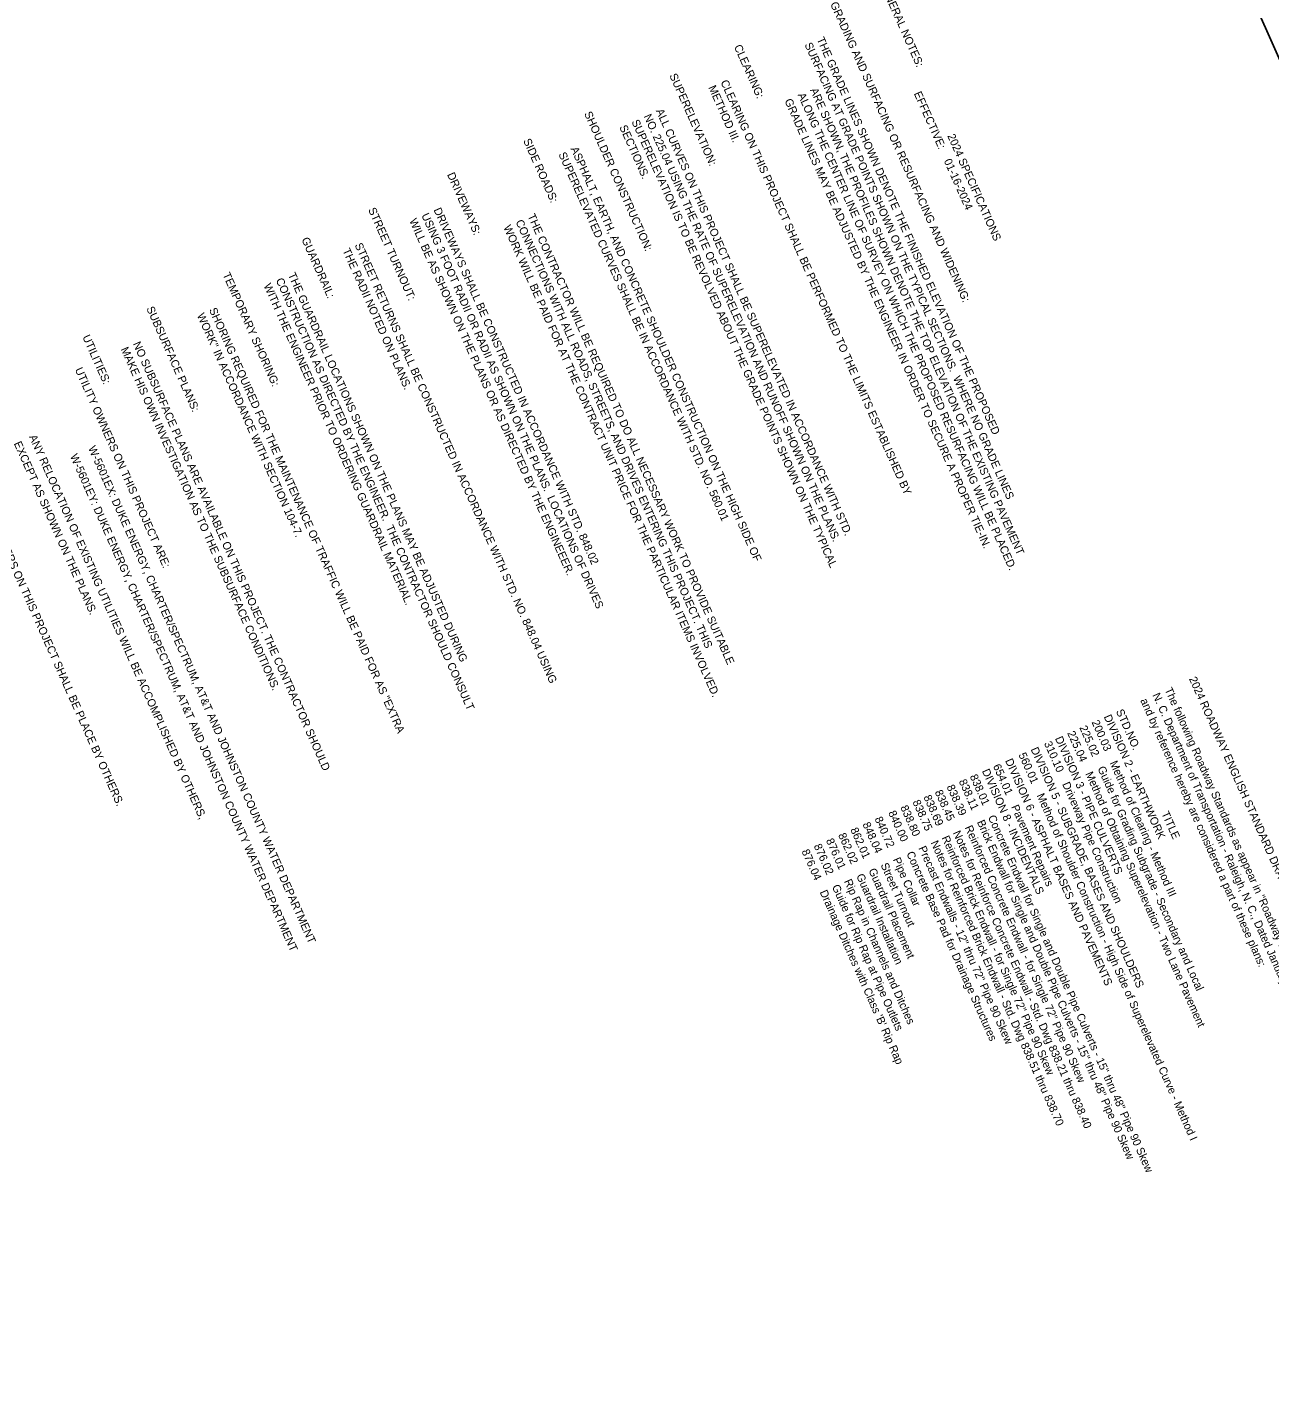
# Model space of a CAD drawing. Extents: x 885268 to 886953, y 552794 to 554777.
# Drawn here: x 885831 to 886576, y 553214 to 554037 of the extents above; entities that cross this region are included whole.
import ezdxf

# ---------------------------------------------------------------- set-up
doc = ezdxf.new("R2010")
doc.units = 0
doc.layers.add('Default', color=7, linetype='Continuous')
doc.layers.add('Sheet Plan CELL', color=7, linetype='Continuous')

msp = doc.modelspace()

# ---------------------------------------------------------------- linework, layer by layer
at = {"layer": 'Sheet Plan CELL'}
msp.add_lwpolyline([(886925.82, 553245.96), (886315.6, 554616.23), (885356.41, 554189.08), (885966.63, 552818.81)], close=True, dxfattribs=at)

# ---------------------------------------------------------------- texts
at = {"layer": 'Default'}
for s, p in [('GENERAL NOTES:                         2024 SPECIFICATIONS', (886341.44, 554064.16)), ('GRADING AND SURFACING OR RESURFACING AND WIDENING:  ', (886312.21, 554051.14)), ('         THE GRADE LINES SHOWN DENOTE THE FINISHED ELEVATION OF THE PROPOSED ', (886297.6, 554044.63)), ('CLEARING:  ', (886254.51, 554025.45)), ('         SURFACING AT GRADE POINTS SHOWN ON THE TYPICAL SECTIONS.  WHERE NO GRADE LINES', (886290.29, 554041.38)), ('SUPERELEVATION:  ', (886215.74, 554008.18)), ('         METHOD III.', (886232.59, 554015.68)), ('         CLEARING ON THIS PROJECT SHALL BE PERFORMED TO THE LIMITS ESTABLISHED BY ', (886239.9, 554018.94)), ('ARE SHOWN, THE PROFILES SHOWN DENOTE THE TOP ELEVATION OF THE EXISTING PAVEMENT', (886300.17, 553999.51)), ('                                       EFFECTIVE:    01-16-2024', (886334.14, 554060.9)), ('GRADE LINES MAY BE ADJUSTED BY THE ENGINEER IN ORDER TO SECURE A PROPER TIE-IN.', (886284.8, 553993.04)), ('ALONG THE CENTER LINE OF SURVEY ON WHICH THE PROPOSED RESURFACING WILL BE PLACED.', (886292.73, 553996.57)), ('SHOULDER CONSTRUCTION:  ', (886164.58, 553985.4)), ('         SUPERELEVATION IS TO BE REVOLVED ABOUT THE GRADE POINTS SHOWN ON THE TYPICAL ', (886186.5, 553995.16)), ('         NO. 225.04 USING THE RATE OF SUPERELEVATION AND RUNOFF SHOWN ON THE PLANS.', (886193.81, 553998.41)), ('         ALL CURVES ON THIS PROJECT SHALL BE SUPERELEVATED IN ACCORDANCE WITH STD. ', (886201.12, 554001.67)), ('         SECTIONS.  ', (886179.2, 553991.9)), ('SIDE ROADS:  ', (886128.04, 553969.12)), ('         SUPERELEVATED CURVES SHALL BE IN ACCORDANCE WITH STD. NO. 560.01', (886142.65, 553975.63)), ('         ASPHALT, EARTH, AND CONCRETE SHOULDER CONSTRUCTION ON THE HIGH SIDE OF', (886149.96, 553978.89)), ('DRIVEWAYS:  ', (886082.35, 553948.78)), ('STREET TURNOUT:  ', (886035.01, 553927.69)), ('         USING 3 FOOT RADII OR RADII AS SHOWN ON THE PLANS.  LOCATIONS OF DRIVES', (886060.42, 553939.01)), ('         DRIVEWAYS SHALL BE CONSTRUCTED IN ACCORDANCE WITH STD. 848.02', (886067.73, 553942.27)), ('THE CONTRACTOR WILL BE REQUIRED TO DO ALL NECESSARY WORK TO PROVIDE SUITABLE', (886130.62, 553924)), ('         WILL BE AS SHOWN ON THE PLANS OR AS DIRECTED BY THE ENGINEEER.', (886053.12, 553935.76)), ('WORK WILL BE PAID FOR AT THE CONTRACT UNIT PRICE FOR THE PARTICULAR ITEMS INVOLVED.', (886116.14, 553917.18)), ('CONNECTIONS WITH ALL ROADS, STREETS, AND DRIVES ENTERING THIS PROJECT. THIS', (886123.45, 553920.44)), ('GUARDRAIL:  ', (885994.98, 553909.87)), ('         STREET RETURNS SHALL BE CONSTRUCTED IN ACCORDANCE WITH STD. NO. 848.04 USING', (886020.39, 553921.19)), ('         THE RADII NOTED ON PLANS.', (886013.08, 553917.93)), ('TEMPORARY SHORING:  ', (885947.64, 553888.79)), ('         WITH THE ENGINEER PRIOR TO ORDERING GUARDRAIL MATERIAL.', (885965.75, 553896.85)), ('         CONSTRUCTION AS DIRECTED BY THE ENGINEER.  THE CONTRACTOR SHOULD CONSULT', (885973.05, 553900.11)), ('         THE GUARDRAIL LOCATIONS SHOWN ON THE PLANS MAY BE ADJUSTED DURING ', (885980.36, 553903.36)), ('SUBSURFACE PLANS:  ', (885901.95, 553868.44)), ('         WORK" IN ACCORDANCE WITH SECTION 104-7.', (885925.72, 553879.02)), ('         SHORING REQUIRED FOR THE MAINTENANCE OF TRAFFIC WILL BE PAID FOR AS "EXTRA ', (885933.02, 553882.28)), ('UTILITIES:  ', (885863.57, 553851.35)), ('         MAKE HIS OWN INVESTIGATION AS TO THE SUBSURFACE CONDITIONS. ', (885880.03, 553858.68)), ('         NO SUBSURFACE PLANS ARE AVAILABLE ON THIS PROJECT. THE CONTRACTOR SHOULD', (885887.33, 553861.93)), ('         UTILITY OWNERS ON THIS PROJECT ARE:  ', (885852.51, 553846.43)), ('         ALL RIGHT-OF-WAY MARKERS ON THIS PROJECT SHALL BE PLACE BY OTHERS.', (885776.24, 553812.46)), ('EXCEPT AS SHOWN ON THE PLANS.', (885822.4, 553787.45)), ('ANY RELOCATION OF EXISTING UTILITIES WILL BE ACCOMPLISHED BY OTHERS,', (885831.51, 553791.5)), ('W-5601EX: DUKE ENERGY, CHARTER/SPECTRUM, AT&T AND JOHNSTON COUNTY WATER DEPARTMENT', (885866.97, 553784.7)), ('W-5601EY: DUKE ENERGY, CHARTER/SPECTRUM, AT&T AND JOHNSTON COUNTY WATER DEPARTMENT', (885856.1, 553779.86)), ('2024 ROADWAY ENGLISH STANDARD DRAWINGS', (886527.52, 553646.3)), ('N. C. Department of Transportation - Raleigh, N. C., Dated January, 2024 are applicable to this project', (886505.6, 553636.54)), ('The following Roadway Standards as appear in "Roadway Standard Drawings" Highway Design Branch -', (886512.91, 553639.79)), ('STD.NO.                       TITLE', (886483.68, 553626.77)), ('and by reference hereby are considered a part of these plans:', (886498.29, 553633.28)), ('200.03    Method of Clearing - Method III', (886469.06, 553620.26)), ('DIVISION 2 - EARTHWORK', (886476.37, 553623.52)), ('DIVISION 3 - PIPE CULVERTS', (886447.14, 553610.5)), ('225.04    Method of Obtaining Superelevation - Two Lane Pavement', (886454.44, 553613.75)), ('225.02    Guide for Grading Subgrade - Secondary and Local', (886461.75, 553617.01)), ('DIVISION 5 - SUBGRADE, BASES AND SHOULDERS', (886432.52, 553603.99)), ('310.10    Driveway Pipe Construction ', (886440.54, 553607.56)), ('654.01    Pavement Repairs', (886409.88, 553593.91)), ('DIVISION 6 - ASPHALT BASES AND PAVEMENTS', (886417.19, 553597.17)), ('560.01    Method of Shoulder Construction - High Side of Superelevated Curve - Method I', (886425.21, 553600.74)), ('838.11    Brick Endwall for Single and Double Pipe Culverts - 15" thru 48" Pipe 90 Skew', (886389.4, 553584.79)), ('838.01    Concrete Endwall for Single and Double Pipe Culverts - 15" thru 48" Pipe 90 Skew', (886395.98, 553587.72)), ('DIVISION 8 - INCIDENTALS', (886403.29, 553590.97)), ('838.45    Notes for Reinforce Concrete Endwall - Std. Dwg 838.21 thru 838.40', (886374.97, 553578.36)), ('838.39    Reinforced Concrete Endwall - for Single 72" Pipe 90 Skew', (886382.09, 553581.53)), ('838.80    Precast Endwalls - 12" thru 72" Pipe 90 Skew', (886354.31, 553569.16)), ('838.75    Notes for Reinforced Brick Endwall - Std. Dwg 838.51 thru 838.70', (886361.62, 553572.42)), ('838.69    Reinforced Brick Endwall - for Single 72" Pipe 90 Skew', (886368.2, 553575.35)), ('840.72    Pipe Collar', (886338.89, 553562.3)), ('840.00    Concrete Base Pad for Drainage Structures', (886347.06, 553565.93)), ('862.02    Guardrail Installation', (886316.99, 553552.54)), ('862.01    Guardrail Placement', (886324.3, 553555.8)), ('848.04    Street Turnout', (886331.6, 553559.05)), ('876.02    Guide for Rip Rap at Pipe Outlets', (886302.37, 553546.03)), ('876.01    Rip Rap in Channels and Ditches', (886309.68, 553549.29)), ("876.04    Drainage Ditches with Class 'B' Rip Rap", (886295.06, 553542.78))]:
    msp.add_text(s, height=4.8, rotation=294.00459, dxfattribs=at).set_placement(p)

doc.saveas('drawing.dxf')
